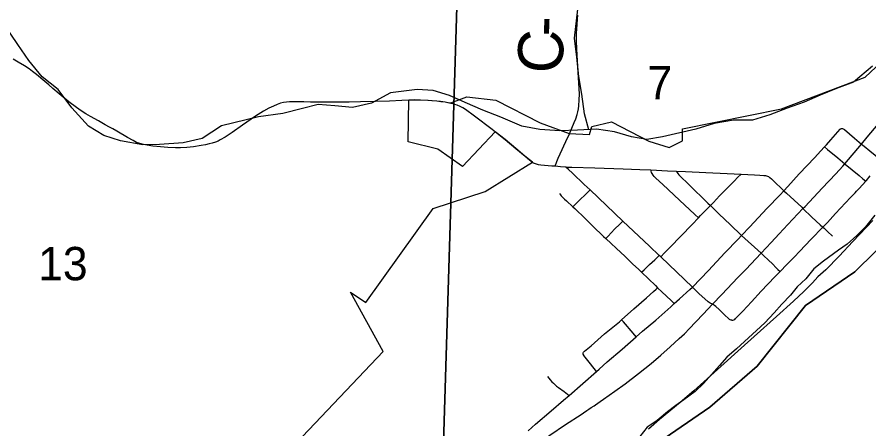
# Model space of a CAD drawing. Extents: x 6.3 to 40.3, y 9 to 31.
# Drawn here: x 10.708 to 11.78, y 25.513 to 26.03 of the extents above; entities that cross this region are included whole.
import ezdxf

# ---------------------------------------------------------------- set-up
doc = ezdxf.new("R2010")
doc.units = 0
for name, color, linetype in [('Default', 7, 'Continuous'), ('GM_X_City_Street', 7, 'Continuous'), ('GM_X_Corporation', 7, 'Continuous'), ('GM_X_County_Road', 7, 'Continuous'), ('GM_X_County_Road_Text', 7, 'Continuous'), ('GM_X_Major_River', 7, 'Continuous'), ('GM_X_Minor_River', 7, 'Continuous'), ('GM_X_Section', 7, 'Continuous'), ('GM_X_Section_Text', 7, 'Continuous'), ('GM_X_State_Route', 7, 'Continuous'), ('SH_Cut_Line', 7, 'Continuous')]:
    doc.layers.add(name, color=color, linetype=linetype)

msp = doc.modelspace()

# ---------------------------------------------------------------- linework, layer by layer
at = {"layer": 'Default'}
msp.add_lwpolyline([(10.9858, 24.8421), (11.0192, 24.8969), (11.0698, 25.0142), (11.1175, 25.0787), (11.1344, 25.1135), (11.171, 25.1528), (11.2115, 25.2141), (11.2461, 25.2602), (11.3094, 25.32), (11.4046, 25.4084), (11.4875, 25.4768), (11.5799, 25.5397), (11.6392, 25.5915), (11.7003, 25.6676), (11.7623, 25.7099), (11.814, 25.7608)], dxfattribs=at)
at = {"layer": 'GM_X_City_Street'}
for points in [[(11.5579, 25.6906), (11.578, 25.7115), (11.5988, 25.7337), (11.6156, 25.7511), (11.6198, 25.7555), (11.6301, 25.7664), (11.6515, 25.7893), (11.6683, 25.8067), (11.673, 25.8117), (11.6779, 25.8171), (11.6922, 25.8328), (11.7117, 25.8536), (11.7189, 25.8614), (11.724, 25.867), (11.7264, 25.8696), (11.7318, 25.8755), (11.7438, 25.8889), (11.7444, 25.8895), (11.745, 25.8899), (11.746, 25.89)], [(11.746, 25.89), (11.7467, 25.8899), (11.7473, 25.8897), (11.7483, 25.8891), (11.749, 25.8885), (11.7618, 25.8776), (11.7704, 25.8704), (11.7737, 25.8676), (11.7809, 25.8617), (11.7877, 25.8564), (11.7932, 25.852), (11.797, 25.8489)], [(11.724, 25.867), (11.7278, 25.8637), (11.7406, 25.8529), (11.7495, 25.8456), (11.7502, 25.845), (11.7674, 25.8308), (11.7722, 25.8268), (11.7759, 25.8238)], [(11.3985, 25.8413), (11.4061, 25.8412), (11.4353, 25.8406), (11.4706, 25.8393), (11.4917, 25.8384), (11.5056, 25.8378), (11.5264, 25.8368), (11.5375, 25.8364), (11.5493, 25.836), (11.5747, 25.8348), (11.6014, 25.8335), (11.619, 25.8327), (11.6361, 25.8319), (11.6425, 25.8315), (11.6477, 25.831), (11.6496, 25.8307), (11.651, 25.8304), (11.6524, 25.83), (11.6535, 25.8295), (11.6544, 25.829), (11.6554, 25.8283), (11.6573, 25.8267), (11.6591, 25.825), (11.673, 25.8117), (11.6762, 25.8086), (11.6953, 25.7909), (11.6969, 25.7894), (11.7082, 25.7785), (11.7187, 25.7688), (11.722, 25.766), (11.7234, 25.7648), (11.7279, 25.7606), (11.734, 25.7546)], [(11.5654, 25.7777), (11.5611, 25.7817), (11.5415, 25.7999), (11.5206, 25.8196), (11.5119, 25.8276), (11.5099, 25.8295), (11.5085, 25.8312), (11.5071, 25.8333), (11.5063, 25.8348), (11.5059, 25.8362), (11.5056, 25.8378)], [(11.518, 25.7287), (11.5229, 25.7336), (11.5299, 25.7407), (11.5433, 25.7545), (11.5574, 25.7695), (11.5654, 25.7777), (11.5682, 25.7806), (11.5787, 25.7912), (11.5805, 25.7931), (11.5843, 25.7971), (11.592, 25.8052), (11.6108, 25.8242), (11.6147, 25.8283), (11.619, 25.8327)], [(11.5375, 25.8364), (11.5386, 25.8347), (11.5395, 25.8334), (11.5406, 25.8319), (11.5421, 25.8303), (11.5532, 25.8194), (11.5773, 25.7961), (11.5805, 25.7931), (11.5917, 25.7823), (11.6052, 25.7694), (11.6198, 25.7555), (11.6442, 25.7334), (11.6478, 25.7299), (11.6531, 25.7248), (11.6588, 25.7193), (11.6628, 25.7153), (11.6652, 25.713), (11.6681, 25.7101)], [(11.6073, 25.649), (11.6081, 25.649), (11.6089, 25.6491), (11.6099, 25.6494), (11.611, 25.6501), (11.612, 25.6511), (11.6212, 25.6604), (11.6323, 25.6722), (11.6444, 25.6854), (11.6616, 25.7035), (11.6681, 25.7101), (11.6768, 25.719), (11.6862, 25.7289), (11.6926, 25.7356), (11.7073, 25.7508), (11.722, 25.766), (11.7237, 25.7677), (11.7276, 25.7717), (11.738, 25.7831), (11.7567, 25.8034), (11.7597, 25.8063), (11.7626, 25.8093), (11.7642, 25.811), (11.7676, 25.8145), (11.7716, 25.819), (11.7759, 25.8238), (11.7768, 25.8248), (11.7815, 25.8304)], [(11.3905, 25.8083), (11.3918, 25.8065), (11.3929, 25.8052), (11.3938, 25.8042), (11.3968, 25.8013), (11.3995, 25.7989), (11.4074, 25.7917), (11.41, 25.7893), (11.4229, 25.7768), (11.4327, 25.7673), (11.4462, 25.7544), (11.4491, 25.7517), (11.4557, 25.7455), (11.4619, 25.7396), (11.4679, 25.7342), (11.4727, 25.7295), (11.4825, 25.72), (11.4903, 25.7127), (11.4937, 25.7094), (11.5113, 25.6925), (11.5141, 25.6899), (11.5194, 25.6849), (11.5311, 25.6738), (11.5351, 25.67)], [(11.4074, 25.7917), (11.415, 25.7991), (11.4247, 25.8084), (11.4292, 25.8128)], [(11.4491, 25.7517), (11.452, 25.7548), (11.4556, 25.7588), (11.4604, 25.7637), (11.4662, 25.7694), (11.4705, 25.7737)], [(11.4937, 25.7094), (11.4971, 25.7125), (11.5039, 25.7189), (11.5105, 25.7251), (11.5159, 25.7306)], [(11.3511, 25.51), (11.3603, 25.5184), (11.3801, 25.5353), (11.3957, 25.5486), (11.4028, 25.5547), (11.4372, 25.5847), (11.4406, 25.5877), (11.4508, 25.5967), (11.4694, 25.6127), (11.4873, 25.6283), (11.4951, 25.6352), (11.5117, 25.6493), (11.5307, 25.6661), (11.5351, 25.67), (11.5418, 25.6761), (11.5547, 25.6877), (11.5579, 25.6906)], [(11.4204, 25.6076), (11.4205, 25.6083), (11.4208, 25.6089), (11.4212, 25.6094), (11.4221, 25.6101), (11.4306, 25.617), (11.4474, 25.6318), (11.4618, 25.6436), (11.4661, 25.6472), (11.4688, 25.6497), (11.4841, 25.6635), (11.5002, 25.6772), (11.509, 25.685), (11.5122, 25.6881), (11.5141, 25.6899)], [(11.6073, 25.649), (11.6066, 25.6491), (11.6055, 25.6495), (11.6045, 25.6501), (11.6036, 25.6508), (11.5982, 25.6559), (11.5916, 25.6624), (11.5874, 25.6664), (11.5858, 25.6675), (11.5832, 25.6691)], [(11.4873, 25.6283), (11.4834, 25.6328), (11.4711, 25.647), (11.4688, 25.6497)], [(11.4372, 25.5847), (11.4341, 25.5886), (11.428, 25.5962), (11.4214, 25.6047), (11.4211, 25.6053), (11.4206, 25.6064), (11.4204, 25.6076)], [(11.3754, 25.5785), (11.3773, 25.5761), (11.379, 25.574), (11.381, 25.5719), (11.3829, 25.5701), (11.3851, 25.5681), (11.387, 25.5664), (11.3894, 25.5645), (11.3964, 25.5594), (11.4028, 25.5547)]]:
    msp.add_lwpolyline(points, dxfattribs=at)
at = {"layer": 'GM_X_Corporation'}
for points in [[(10.9657, 25.3962), (11.169, 25.6097), (11.1277, 25.6842), (11.147, 25.6713), (11.2317, 25.7893), (11.2971, 25.8108), (11.3567, 25.8476), (11.3529, 25.8505), (11.3471, 25.8553), (11.3357, 25.8649), (11.3223, 25.876), (11.3098, 25.8859), (11.2687, 25.8424), (11.2376, 25.8639), (11.2001, 25.873), (11.2012, 25.9261), (11.2084, 25.9262), (11.2158, 25.9261), (11.2251, 25.9257), (11.2302, 25.9253), (11.2362, 25.9247), (11.241, 25.9241), (11.2467, 25.9233), (11.2502, 25.9227), (11.2538, 25.922), (11.2741, 25.9299), (11.3105, 25.9256), (11.3663, 25.8971), (11.4029, 25.8838), (11.4283, 25.8824), (11.4312, 25.8923), (11.4559, 25.8982), (11.5031, 25.8741), (11.5288, 25.866), (11.5455, 25.8746), (11.5454, 25.8895), (11.6699, 25.9148), (11.775, 25.9545), (11.8544, 26.0285)], [(11.814, 25.7608), (11.7623, 25.7099), (11.7003, 25.6676), (11.6392, 25.5915), (11.5799, 25.5397), (11.4875, 25.4768)]]:
    msp.add_lwpolyline(points, dxfattribs=at)
at = {"layer": 'GM_X_County_Road'}
for points in [[(11.4031, 25.8833), (11.4092, 25.8973), (11.411, 25.9019), (11.4129, 25.9074), (11.4138, 25.9107), (11.4146, 25.9146), (11.4151, 25.9186), (11.4155, 25.9259), (11.4157, 25.933), (11.415, 25.9475), (11.4142, 25.9604), (11.4125, 25.9894), (11.4122, 25.9999), (11.4121, 26.0029), (11.4121, 26.0088), (11.4122, 26.0112), (11.4123, 26.0131), (11.4124, 26.0149), (11.4128, 26.0211), (11.4133, 26.0273), (11.4138, 26.0322)], [(11.385, 25.8425), (11.3875, 25.8485), (11.3891, 25.8525), (11.3917, 25.8581), (11.3987, 25.8734), (11.4031, 25.8833)]]:
    msp.add_lwpolyline(points, dxfattribs=at)
at = {"layer": 'GM_X_Major_River'}
msp.add_lwpolyline([(11.7874, 25.7812), (11.7755, 25.7662), (11.7647, 25.7557), (11.7524, 25.7445), (11.7416, 25.7371), (11.7228, 25.7231), (11.7105, 25.7138), (11.7005, 25.7011), (11.6897, 25.691), (11.6811, 25.6806), (11.6703, 25.6694), (11.6607, 25.6583), (11.6491, 25.6459), (11.6383, 25.6362), (11.6286, 25.627), (11.6133, 25.613), (11.601, 25.6026), (11.5921, 25.5922), (11.582, 25.581), (11.572, 25.5694), (11.5612, 25.5597), (11.5469, 25.5489), (11.5368, 25.5419), (11.5264, 25.5341), (11.5133, 25.5232), (11.5009, 25.5147), (11.4916, 25.5031)], dxfattribs=at)
at = {"layer": 'GM_X_Minor_River'}
for points in [[(11.4274, 25.8884), (11.4219, 25.9085), (11.4189, 25.933), (11.4151, 25.9553), (11.4124, 25.9795), (11.4094, 26.0032), (11.4136, 26.0398)], [(11.7842, 25.9681), (11.7603, 25.9481), (11.7391, 25.9402), (11.7187, 25.9319), (11.6983, 25.9232), (11.6771, 25.9156), (11.6551, 25.9073), (11.6335, 25.9006), (11.6097, 25.9002), (11.5851, 25.896), (11.562, 25.8892), (11.5203, 25.8794), (11.5006, 25.876), (11.4813, 25.8794), (11.4598, 25.8859), (11.4374, 25.8889), (11.4132, 25.8877), (11.3909, 25.887), (11.3659, 25.8885), (11.3431, 25.893), (11.317, 25.904), (11.2943, 25.913), (11.272, 25.9225), (11.2523, 25.9315), (11.2318, 25.9376), (11.2118, 25.9391), (11.1781, 25.9346), (11.1542, 25.9217), (11.1304, 25.9164), (11.1081, 25.9183), (11.0869, 25.9202), (11.0675, 25.9149), (11.0426, 25.9089), (11.0119, 25.9047), (10.9653, 25.8934), (10.9411, 25.8772), (10.9173, 25.8719), (10.8873, 25.87), (10.8665, 25.8696), (10.8385, 25.8746), (10.8173, 25.881), (10.798, 25.8927), (10.7772, 25.9157), (10.7601, 25.9391), (10.7401, 25.9549), (10.723, 25.9753), (10.7094, 25.9953), (10.6909, 26.0225)]]:
    msp.add_lwpolyline(points, dxfattribs=at)
at = {"layer": 'GM_X_Section'}
msp.add_lwpolyline([(10.2824, 26.2364), (11.2666, 26.2073), (11.242, 25.3993), (11.2405, 25.3466), (11.2394, 25.3243), (11.2143, 25.2557), (11.1962, 25.2251), (10.2864, 25.2447)], close=True, dxfattribs=at)
for points in [[(11.242, 25.3993), (11.2666, 26.2073)], [(11.7847, 25.7745), (11.7598, 25.7479), (11.7423, 25.7294), (11.7255, 25.7125), (11.7158, 25.7036), (11.7087, 25.6959), (11.6979, 25.6852), (11.6848, 25.6732), (11.6635, 25.6539), (11.6355, 25.6285), (11.619, 25.6138), (11.5936, 25.591), (11.5596, 25.5605), (11.5424, 25.5459), (11.5166, 25.5242), (11.5024, 25.5123)]]:
    msp.add_lwpolyline(points, dxfattribs=at)
at = {"layer": 'GM_X_State_Route'}
msp.add_line((11.5832, 25.6691), (11.5949, 25.6815), dxfattribs=at)
for points in [[(11.2023, 25.9256), (11.2014, 25.9255), (11.1923, 25.9252), (11.1767, 25.9244), (11.1594, 25.9237), (11.1402, 25.9233), (11.1259, 25.923), (11.1024, 25.9228), (11.0845, 25.923), (11.0775, 25.9231), (11.069, 25.9233), (11.0621, 25.9235), (11.0547, 25.9235), (11.051, 25.9234), (11.0473, 25.9232), (11.0434, 25.9226), (11.0396, 25.9216), (11.0356, 25.9201), (11.031, 25.9181), (11.025, 25.9153), (11.0182, 25.9117), (11.0082, 25.9054), (10.9921, 25.8942), (10.9791, 25.885), (10.9702, 25.879), (10.964, 25.8756), (10.9611, 25.874), (10.9581, 25.8728), (10.9539, 25.8715), (10.9499, 25.8705), (10.9455, 25.8695), (10.9401, 25.8685), (10.9304, 25.867), (10.9219, 25.8661), (10.9141, 25.8656), (10.9077, 25.8655), (10.8978, 25.8659), (10.8886, 25.8667), (10.8791, 25.8679), (10.8721, 25.8689), (10.8672, 25.8697), (10.8629, 25.8709), (10.8587, 25.8725), (10.8542, 25.8747), (10.8472, 25.8788), (10.8337, 25.8866), (10.8289, 25.8893), (10.8246, 25.8918), (10.8191, 25.8947), (10.8106, 25.8994), (10.8008, 25.9051), (10.7949, 25.9085), (10.7891, 25.9122), (10.783, 25.9165), (10.7735, 25.9236), (10.7614, 25.9333), (10.7533, 25.9401), (10.7481, 25.9446), (10.7407, 25.9511), (10.7327, 25.9579), (10.7279, 25.9617), (10.7234, 25.9649), (10.7177, 25.9686), (10.7098, 25.9734), (10.7033, 25.9769)], [(11.6779, 25.7693), (11.6969, 25.7894), (11.6995, 25.7921), (11.7212, 25.8151), (11.7384, 25.8331), (11.7469, 25.8426), (11.7495, 25.8456), (11.7704, 25.8704), (11.7775, 25.8789), (11.7914, 25.8953), (11.8032, 25.9091), (11.8128, 25.9206), (11.8168, 25.9253), (11.8342, 25.9457), (11.8381, 25.9504), (11.855, 25.9704), (11.8576, 25.9735)], [(11.2549, 25.9212), (11.254, 25.9214), (11.2504, 25.9222), (11.2469, 25.9228), (11.2412, 25.9236), (11.2364, 25.9241), (11.2304, 25.9248), (11.2253, 25.9252), (11.216, 25.9256), (11.2086, 25.9257), (11.2023, 25.9256)], [(11.31, 25.8853), (11.3058, 25.8885), (11.2838, 25.9055), (11.2723, 25.9138), (11.2692, 25.9158), (11.2658, 25.9176), (11.2621, 25.9192), (11.2591, 25.9202), (11.2567, 25.9208), (11.2549, 25.9212)], [(11.3575, 25.8467), (11.3569, 25.847), (11.3531, 25.85), (11.3473, 25.8547), (11.3359, 25.8644), (11.3225, 25.8755), (11.31, 25.8853)], [(11.5832, 25.6691), (11.5802, 25.6706), (11.5776, 25.6723), (11.5661, 25.6828), (11.5579, 25.6906), (11.518, 25.7287), (11.5159, 25.7306), (11.504, 25.742), (11.4705, 25.7737), (11.4499, 25.7933), (11.4292, 25.8128), (11.4218, 25.8197), (11.4068, 25.8338), (11.4018, 25.8384), (11.3985, 25.8413), (11.3921, 25.8419), (11.385, 25.8425), (11.3812, 25.8428), (11.3672, 25.8439), (11.3641, 25.8443), (11.3616, 25.845), (11.3593, 25.8458), (11.3581, 25.8463), (11.3575, 25.8467)], [(11.5949, 25.6815), (11.615, 25.7028), (11.6249, 25.713), (11.6442, 25.7334), (11.6569, 25.7469), (11.667, 25.7578), (11.6779, 25.7693)], [(11.3588, 25.4914), (11.398, 25.5179), (11.4177, 25.5308), (11.4208, 25.5329), (11.425, 25.5356), (11.4276, 25.5373), (11.4306, 25.5393), (11.4342, 25.5417), (11.4358, 25.5428), (11.4389, 25.5448), (11.4419, 25.547), (11.4459, 25.5499), (11.4602, 25.5598), (11.4734, 25.5692), (11.4901, 25.582), (11.5061, 25.5948), (11.5183, 25.6054), (11.5298, 25.6158), (11.5413, 25.6263), (11.5477, 25.6321), (11.5486, 25.633), (11.5533, 25.6379), (11.5714, 25.6567), (11.5832, 25.6691)]]:
    msp.add_lwpolyline(points, dxfattribs=at)
at = {"layer": 'SH_Cut_Line'}
msp.add_lwpolyline([(10.9858, 24.8421), (11.0192, 24.8969), (11.0698, 25.0142), (11.1175, 25.0787), (11.1344, 25.1135), (11.171, 25.1528), (11.2115, 25.2141), (11.2461, 25.2602), (11.3094, 25.32), (11.4046, 25.4084), (11.4875, 25.4768), (11.5799, 25.5397), (11.6392, 25.5915), (11.7003, 25.6676), (11.7623, 25.7099), (11.814, 25.7608)], dxfattribs=at)

# ---------------------------------------------------------------- texts
at = {"layer": 'GM_X_County_Road_Text'}
for s, rotation, p in [('-', 87.9316, (11.396, 26.0048)), ('C', 88.0181, (11.3944, 25.9585))]:
    msp.add_text(s, height=0.0568, rotation=rotation, dxfattribs=at).set_placement(p)
at = {"layer": 'GM_X_Section_Text'}
for s, height, p in [('7', 0.0419, (11.5014, 25.9265)), ('13', 0.04186, (10.7348, 25.6993))]:
    msp.add_text(s, height=height, rotation=0, dxfattribs=at).set_placement(p)

doc.saveas('drawing.dxf')
